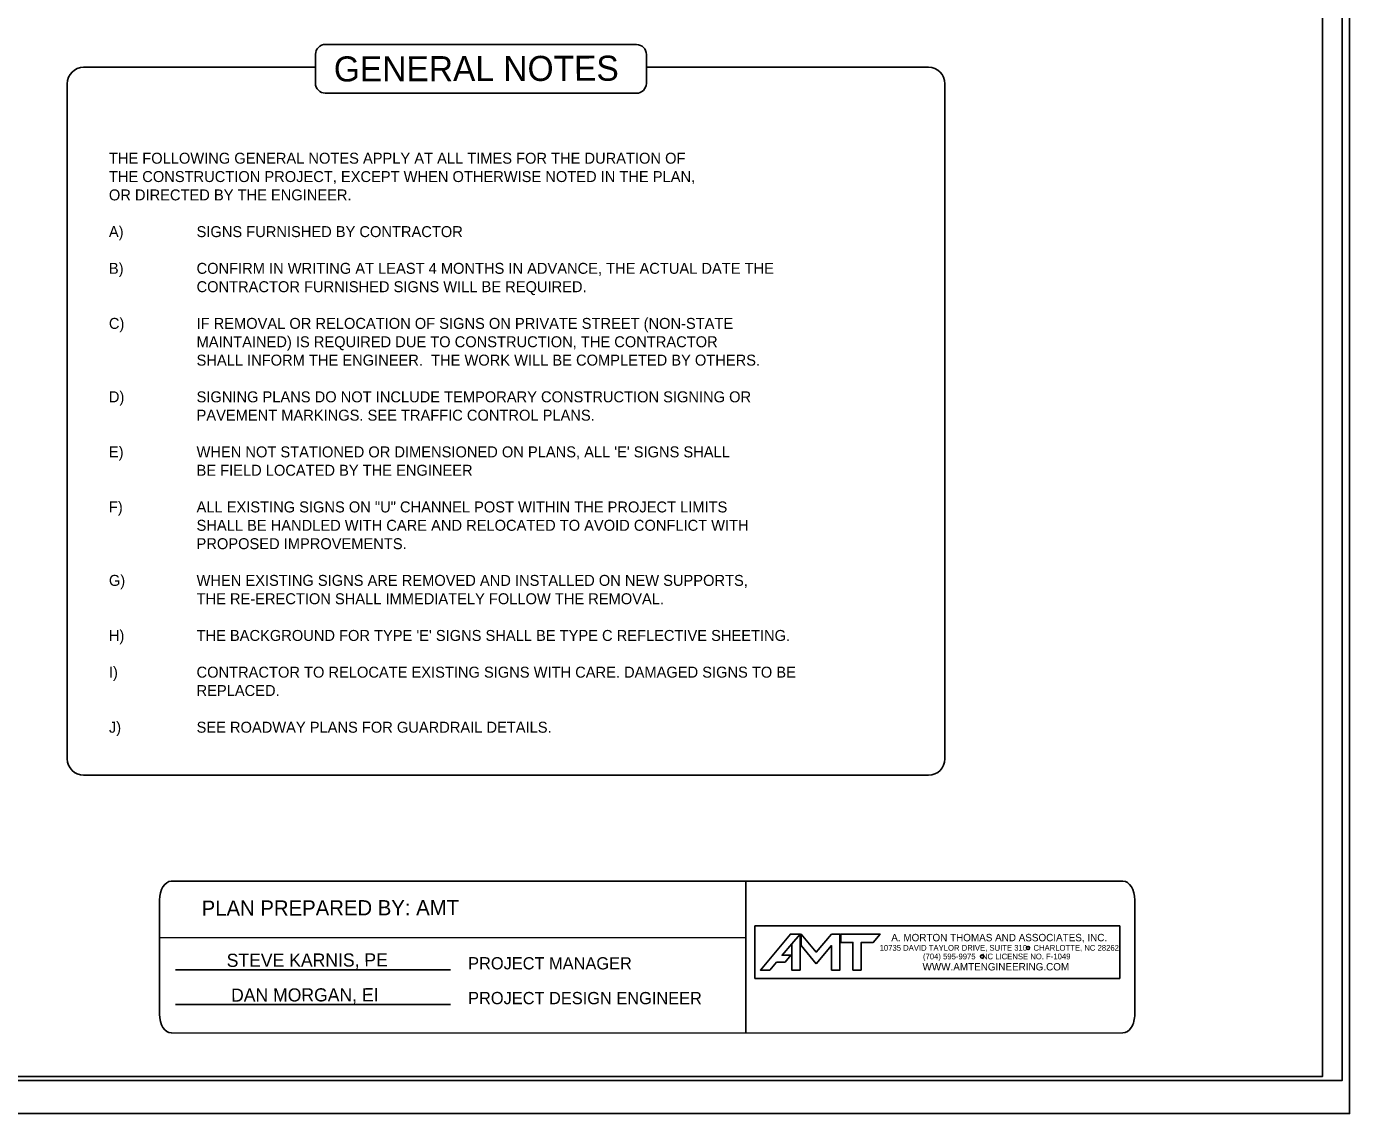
# Model space of a CAD drawing. Extents: x 2088591 to 2091186, y 751169 to 752405.
# Drawn here: x 2089946 to 2090752, y 751309 to 751970 of the extents above; entities that cross this region are included whole.
import ezdxf

# ---------------------------------------------------------------- set-up
doc = ezdxf.new("R2010")
doc.units = 0
for name, color, linetype in [('Default', 7, 'Continuous'), ('Sheet Block Title CELL', 7, 'Continuous'), ('Sheet Plot Border Outside CELL', 7, 'Continuous'), ('Sheet Sticker Incomplete CELL', 7, 'Continuous'), ('Sheet Title CELL', 7, 'Continuous'), ('Typical Detail Wedge1 CELL', 7, 'Continuous')]:
    doc.layers.add(name, color=color, linetype=linetype)

msp = doc.modelspace()

# ---------------------------------------------------------------- linework, layer by layer
at = {"layer": 'Default'}
for p, q in [((2090034.34, 751450.12), (2090613.61, 751450.22)), ((2090384.11, 751357.83), (2090384.09, 751450.18)), ((2090027.17, 751369.31), (2090027.15, 751438.68)), ((2090620.81, 751438.73), (2090620.83, 751369.36)), ((2090027.14, 751415.76), (2090384.1, 751415.92)), ((2090036.99, 751396.36), (2090204.37, 751396.29)), ((2090036.98, 751375.18), (2090204.36, 751375.09)), ((2090613.52, 751357.87), (2090034.37, 751357.76))]:
    msp.add_line(p, q, dxfattribs=at)
for centre, major_axis, start_param, end_param in [((2090034.35, 751438.68), (0.01, 11.49), 0.000702, 1.571498), ((2090613.61, 751438.73), (0.01, 11.49), 4.713091, 6.283887), ((2090034.37, 751369.31), (-0.01, -11.49), 4.713091, 6.283887), ((2090613.63, 751369.36), (-0.01, -11.49), 6.268607, 7.854684)]:
    msp.add_ellipse(centre, major_axis=major_axis, ratio=0.62659, start_param=start_param, end_param=end_param, dxfattribs=at)
at = {"layer": 'Sheet Block Title CELL'}
msp.add_lwpolyline([(2090751.52, 752404.71), (2089068.61, 752404.71), (2089068.61, 751308.81), (2090751.52, 751308.81)], close=True, dxfattribs=at)
at = {"layer": 'Sheet Plot Border Outside CELL'}
msp.add_lwpolyline([(2090389.58, 751422.99), (2090611.62, 751422.99), (2090611.62, 751391.03), (2090389.58, 751391.03)], close=True, dxfattribs=at)
at = {"layer": 'Sheet Sticker Incomplete CELL'}
for points in [[(2090735.1, 752381.4), (2089235.1, 752381.4), (2089235.1, 751331.4), (2090735.1, 751331.4)], [(2090389.58, 751422.99), (2090611.62, 751422.99), (2090611.62, 751391.03), (2090389.58, 751391.03)]]:
    msp.add_lwpolyline(points, close=True, dxfattribs=at)
for points in [[(2090412.01, 751412.13), (2090417.05, 751418.03), (2090411.16, 751418.03), (2090392.94, 751396.08), (2090398.64, 751396.08), (2090402.72, 751401.01), (2090407.94, 751401.01), (2090411.53, 751405.16), (2090406.13, 751405.16), (2090412.01, 751412.13)], [(2090417.04, 751396.08), (2090417.05, 751418.03), (2090412.01, 751412.13), (2090412.01, 751396.08), (2090417.04, 751396.08)], [(2090426.91, 751399.94), (2090436.24, 751411.06), (2090436.24, 751396.07), (2090441.27, 751396.07), (2090441.27, 751418.03), (2090436.24, 751418.03), (2090426.91, 751407.07), (2090417.69, 751418.03), (2090417.69, 751411.04), (2090426.91, 751399.94)], [(2090454.31, 751396.07), (2090454.31, 751412.99), (2090461.6, 751412.99), (2090465.81, 751418.03), (2090441.92, 751418.03), (2090441.92, 751412.99), (2090449.27, 751412.99), (2090449.27, 751396.07), (2090454.31, 751396.07)]]:
    msp.add_lwpolyline(points, dxfattribs=at)
for centre in [(2090527.9, 751404.33), (2090555.81, 751409.55)]:
    msp.add_circle(centre, 1, dxfattribs=at)
at = {"layer": 'Sheet Title CELL'}
for p, q in [((2090122.09, 751935.79), (2090122.1, 751953.42)), ((2090323.49, 751935.69), (2090323.5, 751953.33))]:
    msp.add_line(p, q, dxfattribs=at)
for points in [[(2090128.11, 751959.42), (2090317.5, 751959.33)], [(2089981, 751945.54), (2090122.1, 751945.54)], [(2090323.5, 751945.54), (2090495.24, 751945.54)], [(2089971, 751524.69), (2089971, 751935.54)], [(2090128.09, 751929.78), (2090317.49, 751929.7)], [(2090505.24, 751935.54), (2090505.24, 751524.69)], [(2090495.24, 751514.69), (2089981, 751514.69)]]:
    msp.add_lwpolyline(points, dxfattribs=at)
for centre, radius, start, end in [((2090128.1, 751953.42), 6, 89.97341, 179.97341), ((2090317.5, 751953.33), 6, 359.97341, 89.97341), ((2089981, 751935.54), 10, 90, 180), ((2090495.24, 751935.54), 10, 0, 90), ((2090128.09, 751935.78), 6, 179.97341, 269.97341), ((2090317.49, 751935.7), 6, 269.97341, 359.97341), ((2089981, 751524.69), 10, 180, 270), ((2090495.24, 751524.69), 10, 270, 0)]:
    msp.add_arc(centre, radius, start, end, dxfattribs=at)
at = {"layer": 'Typical Detail Wedge1 CELL'}
msp.add_lwpolyline([(2090747.03, 752384.71), (2089081.6, 752384.71), (2089081.6, 751328.81), (2090747.03, 751328.81)], close=True, dxfattribs=at)

# ---------------------------------------------------------------- texts
at = {"layer": 'Default'}
for s, height, rotation, p in [('GENERAL NOTES', 15.2572, 0.15565, (2090133.28, 751936.89)), ('PLAN PREPARED BY: AMT', 9.2466, 0.15565, (2090052.83, 751429.15)), ('STEVE KARNIS, PE', 8, 0.15565, (2090068.06, 751398.06)), ('PROJECT MANAGER', 7.4502, 359.97341, (2090215.02, 751396.54)), ('DAN MORGAN, EI', 8, 0.15565, (2090070.74, 751376.88)), ('PROJECT DESIGN ENGINEER', 7.4502, 359.97341, (2090215.01, 751375.37))]:
    msp.add_text(s, height=height, rotation=rotation, dxfattribs=at).set_placement(p)
at = {"layer": 'Sheet Sticker Incomplete CELL'}
for s, height, p in [('A. MORTON THOMAS AND ASSOCIATES, INC.', 4.5, (2090472.59, 751413.64)), ('10735 DAVID TAYLOR DRIVE, SUITE 310   CHARLOTTE, NC 28262', 3.5, (2090465.49, 751407.89)), ('(704) 595-9975   NC LICENSE NO. F-1049', 3.5, (2090491.88, 751402.64)), ('WWW.AMTENGINEERING.COM', 4.5, (2090491.61, 751395.89))]:
    msp.add_text(s, height=height, rotation=359.99952, dxfattribs=at).set_placement(p)
at = {"layer": 'Sheet Title CELL'}
for s, height, p in [('THE FOLLOWING GENERAL NOTES APPLY AT ALL TIMES FOR THE DURATION OF', 6.6709, (2089996.36, 751886.86)), ('THE CONSTRUCTION PROJECT, EXCEPT WHEN OTHERWISE NOTED IN THE PLAN,', 6.6709, (2089996.36, 751875.69)), ('OR DIRECTED BY THE ENGINEER.', 6.6709, (2089996.36, 751864.52)), ('A)', 6.671, (2089996.36, 751842.18)), ('SIGNS FURNISHED BY CONTRACTOR', 6.6709, (2090049.72, 751842.18)), ('B) ', 6.671, (2089996.36, 751819.84)), ('CONFIRM IN WRITING AT LEAST 4 MONTHS IN ADVANCE, THE ACTUAL DATE THE', 6.6709, (2090049.72, 751819.84)), ('CONTRACTOR FURNISHED SIGNS WILL BE REQUIRED.', 6.6709, (2090049.72, 751808.67)), ('C)', 6.671, (2089996.36, 751786.33)), ('IF REMOVAL OR RELOCATION OF SIGNS ON PRIVATE STREET (NON-STATE ', 6.6709, (2090049.72, 751786.33)), ('MAINTAINED) IS REQUIRED DUE TO CONSTRUCTION, THE CONTRACTOR ', 6.6709, (2090049.72, 751775.15)), ('SHALL INFORM THE ENGINEER.  THE WORK WILL BE COMPLETED BY OTHERS.', 6.6709, (2090049.72, 751763.98)), ('D)', 6.671, (2089996.36, 751741.64)), ('SIGNING PLANS DO NOT INCLUDE TEMPORARY CONSTRUCTION SIGNING OR ', 6.6709, (2090049.72, 751741.64)), ('PAVEMENT MARKINGS. SEE TRAFFIC CONTROL PLANS.', 6.6709, (2090049.72, 751730.47)), ('E)', 6.671, (2089996.36, 751708.13)), ("WHEN NOT STATIONED OR DIMENSIONED ON PLANS, ALL 'E' SIGNS SHALL", 6.6709, (2090049.72, 751708.13)), ('BE FIELD LOCATED BY THE ENGINEER', 6.6709, (2090049.72, 751696.96)), ('F)', 6.671, (2089996.36, 751674.62)), ('ALL EXISTING SIGNS ON "U" CHANNEL POST WITHIN THE PROJECT LIMITS', 6.6709, (2090049.72, 751674.62)), ('SHALL BE HANDLED WITH CARE AND RELOCATED TO AVOID CONFLICT WITH', 6.6709, (2090049.72, 751663.45)), ('PROPOSED IMPROVEMENTS.', 6.6709, (2090049.72, 751652.27)), ('G)', 6.671, (2089996.36, 751629.93)), ('WHEN EXISTING SIGNS ARE REMOVED AND INSTALLED ON NEW SUPPORTS, ', 6.6709, (2090049.72, 751629.93)), ('THE RE-ERECTION SHALL IMMEDIATELY FOLLOW THE REMOVAL.', 6.6709, (2090049.72, 751618.76)), ('H)', 6.671, (2089996.36, 751596.42)), ("THE BACKGROUND FOR TYPE 'E' SIGNS SHALL BE TYPE C REFLECTIVE SHEETING.", 6.6709, (2090049.72, 751596.42)), ('I)', 6.671, (2089996.36, 751574.08)), ('CONTRACTOR TO RELOCATE EXISTING SIGNS WITH CARE. DAMAGED SIGNS TO BE', 6.6709, (2090049.72, 751574.08)), ('REPLACED.', 6.671, (2090049.72, 751562.91)), ('J)', 6.671, (2089996.36, 751540.57)), ('SEE ROADWAY PLANS FOR GUARDRAIL DETAILS.', 6.6709, (2090049.72, 751540.57))]:
    msp.add_text(s, height=height, dxfattribs=at).set_placement(p)

doc.saveas('drawing.dxf')
